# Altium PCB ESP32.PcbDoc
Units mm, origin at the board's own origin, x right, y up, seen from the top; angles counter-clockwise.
Board outline 55.37 x 35.69 mm, 2 copper layers (Top Layer, Bottom Layer); 35 components, 23 nets, 179 pads, 51 vias.
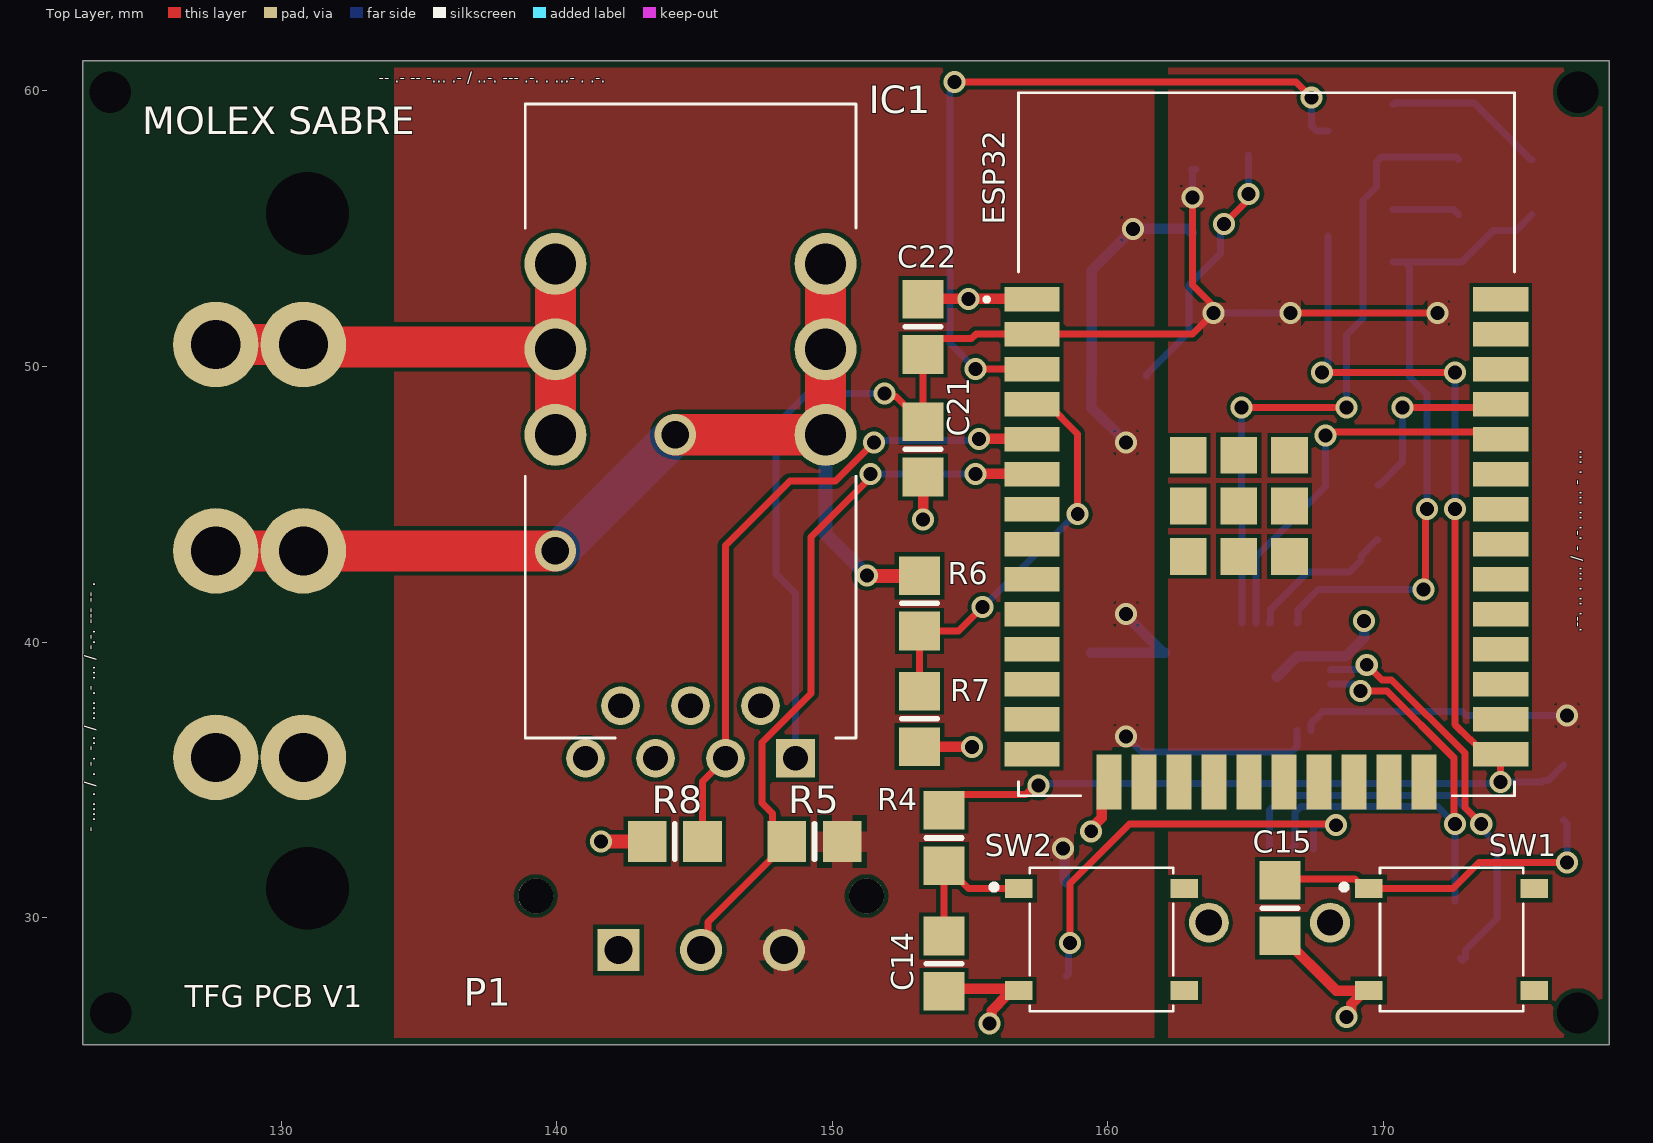
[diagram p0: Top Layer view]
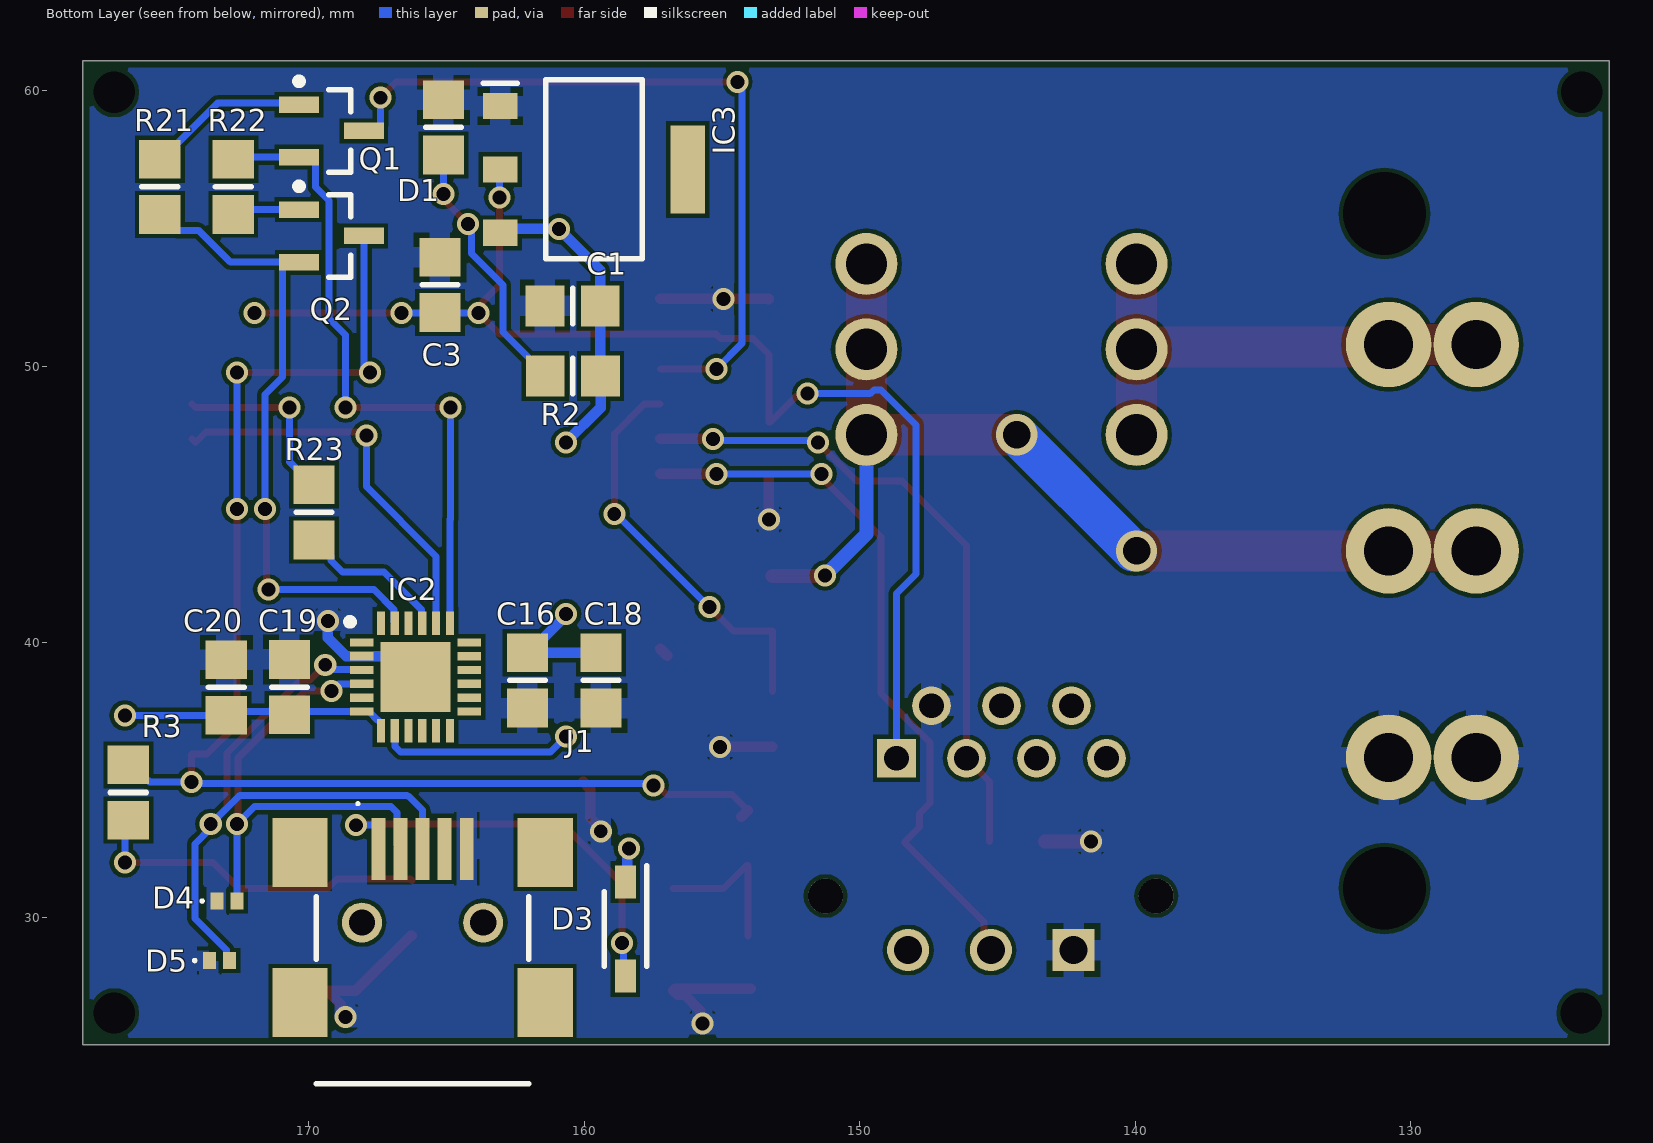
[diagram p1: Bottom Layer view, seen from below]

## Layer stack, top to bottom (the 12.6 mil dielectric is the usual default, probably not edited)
Top Solder: solder mask 0.0102, Solder Resist, Dk 3.5
Top Layer: signal copper 0.0356
Dielectric 1: dielectric 0.32, FR-4, Dk 4.8
Bottom Layer: signal copper 0.0356
Bottom Solder: solder mask 0.0102, Solder Resist, Dk 3.5

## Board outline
122.809,25.4 178.181,25.4 178.181,61.087 122.809,61.087

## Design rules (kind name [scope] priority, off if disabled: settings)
BoardOutlineClearance [All] p1: gap=0.25 ignorepadtopadclearanceinfootprint=FALSE except(0: Arc-SplitContinuation Track-SplitContinuation SMDPad-SplitContinuation THPad-SplitContinuation Via-SplitContinuation Fill-SplitContinuation Poly-SplitContinuation Region-SplitContinuation Text-SplitContinuation)
Clearance Clearance-xPP-xTP-xTT [All] p1: gap=0.15 ignorepadtopadclearanceinfootprint=FALSE except(0: Arc-Hole Track-Hole SMDPad-Hole THPad-Hole Via-Hole Fill-Hole Poly-Hole Region-Hole Text-Hole)
ComponentClearance [All] p1: gap=0.25 collisioncheckmode=3 verticalgap=0.25 showdistances=FALSE
DiffPairsRouting [All] p1: maxlimit=0.25 minlimit=0.25 mostfreqgap=0.25 toplayer_minwidth=0.381 toplayer_maxwidth=0.381 toplayer_prefwidth=0.381 bottomlayer_minwidth=0.381 bottomlayer_maxwidth=0.381 bottomlayer_prefwidth=0.381 maxuncoupledlength=12.5
Height [All] p1: minheight=0 maxheight=100 prefheight=12.5
HoleSize HoleSize-PTH [All] p1: absolutevalues=TRUE maxlimit=4.01 minlimit=0.25 maxpercent=80.000 minpercent=20.000
HoleToHoleClearance [All] p1: gap=0.35 allowstackedmicrovias=TRUE
MinimumAnnularRing "Minimum IAR  >0.45mm" [((ObjectKind = 'Pad') OR (ObjectKind = 'Via')) And (Layer = 'MultiLayer') And (HoleDiameter > AsMM(0.45))] p1: minimumring=0.175 // minimum inner annular ring for pads > 0.45mm finished hole size
MinimumAnnularRing "Minimum IAR <=0.45mm" [((ObjectKind = 'Pad') OR (ObjectKind = 'Via')) And (Layer = 'MultiLayer') And (HoleDiameter <= AsMM(0.45))] p2: minimumring=0.175 // minimum inner annular ring for pads <= 0.45mm finished hole size
MinimumSolderMaskSliver [All] p1: minsoldermaskwidth=0.08
PlaneClearance PlaneClearance-IPI [All] p1: clearance=0.25
PlaneConnect [All] p1: planeconnectstyle=Relief reliefexpansion=0.175 reliefentries=4 reliefconductorwidth=0.2 reliefairgap=0.2
PolygonConnect PolygonConnect-xTW [All] p1: connectstyle=Relief reliefconductorwidth=0.762 reliefentries=4 polygonreliefangle="90 Angle" airgapwidth=0.2
RoutingCorners [All] p1: cornerstyle=45-Degree minsetback=2.5 maxsetback=2.5
RoutingVias "RoutingVias > 0.45mm" [(ObjectKind = 'Via') And (HoleDiameter > AsMM(0.45))] p1: holewidth=0.5 width=0.85 viastyle="Through Hole" minholewidth=0.5 minwidth=0.8 maxholewidth=0.9 maxwidth=1.25 // finishet hole size > 0.45mm
RoutingVias "RoutingVias <= 0.45mm" [(ObjectKind = 'Via') And (HoleDiameter <= AsMM(0.45))] p2: holewidth=0.3 width=0.65 viastyle="Through Hole" minholewidth=0.3 minwidth=0.6 maxholewidth=0.45 maxwidth=0.8 // finishet hole size <= 0.45mm
SilkToSilkClearance [All] p1: silktosilkclearance=0.2
SilkToSolderMaskClearance SilkscreenOverComponentPads [IsPad] p1: minsilkscreentomaskgap=0.2 clearancetoexposedcopper=TRUE
SolderMaskExpansion [All] p1: expansion=0 istentingtop=FALSE
UnRoutedNet [All] p1: checkbadconnections=TRUE
Width Width-xTW [All] p1: maxlimit=3 minlimit=0.15 preferedwidth=0.254
18 further rules are at their usual default settings.

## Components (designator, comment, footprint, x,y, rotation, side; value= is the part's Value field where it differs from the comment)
C1 "Cap" 6-0805_M 160.417,52.197 r180 bottom value=10uF
C3 "Cap" 6-0805_M 165.227,52.959 r270 bottom value=22uF
C14 "Cap" 6-0805_M 154.051,28.337 r90 top value=1nF
C15 "Cap" 6-0805_M 166.243,30.353 r90 top value=1nF
C16 "Cap" 6-0805_M 162.052,38.608 r90 bottom value=0.1uF
C18 "Cap" 6-0805_M 159.385,38.608 r90 bottom value=10uF
C19 "Cap" 6-0805_M 170.688,38.37 r270 bottom value=10uF
C20 "Cap" 6-0805_M 172.974,38.354 r270 bottom value=0.1uF
C21 "Cap" 6-0805_M 153.289,46.99 r90 top value=100uF
C22 "Cap" 6-0805_M 153.289,51.435 r270 top value=1uF
D1 "LED0" 6-0805_M 165.1,58.674 r90 bottom
D3 "1N5819HW-7-F" SOD3716X145N 158.496,29.591 r270 bottom
D4 "ESD5581N2T5G" ESD5581N2T5G 172.958,30.607 r180 bottom
D5 "ESD5581N2T5G" ESD5581N2T5G 173.228,28.448 r180 bottom
ESP32 "ESP32-WROOM-32D__4MB_PS_" ESP32WROOM32D4MBPS 165.75,47.18 r0 top
IC1 "HO_8-NP_SP33_1000" HO8NPSP33-1000 148.664,35.785 r90 top
IC2 "CP2102N-A02-GQFN24R" QFN50P400X400X80-25N-D 166.116,38.735 r180 bottom
IC3 "NCP1117ST33T3G" SOT230P700X180-4N 159.639,57.15 r180 bottom
J1 "10033526-N3212MLF" 10033526N3212MLF 165.857,33.174 r180 bottom
"MOLEX SABRE" "PANEL" 43160-4303 134.985,29.017 r90 top
P1 "DS18B20" 43650-0315 145.24,28.829 r180 top
Q1 "NPN" SOT-23_M 169.164,58.547 r180 bottom
Q2 "NPN" SOT-23_M 169.164,54.737 r180 bottom
R2 "Res1" 6-0805_M 160.401,49.657 r180 bottom value=2K
R3 "Res1" 6-0805_M 176.53,34.544 r90 bottom value=470
R4 "Res1" 6-0805_M 154.051,32.893 r90 top value=470
R5 "Res2" 6-0805_M 149.352,32.766 r180 top value=4.7K
R6 "Res2" 6-0805_M 153.162,41.402 r90 top value=189K
R7 "Res2" 6-0805_M 153.162,37.211 r90 top value=11K
R8 "Res2" 6-0805_M 144.288,32.766 r0 top value=10K
R21 "Res1" 6-0805_M 175.387,56.515 r90 bottom value=12K
R22 "Res1" 6-0805_M 172.72,56.515 r270 bottom value=12K
R23 "Res1" 6-0805_M 169.799,44.704 r90 bottom value=470
SW1 "PTS526_SK15_SMTR2_LFS" PTS526SK15SMTR2LFS 172.466,29.21 r0 top
SW2 "PTS526_SK15_SMTR2_LFS" PTS526SK15SMTR2LFS 159.766,29.21 r0 top

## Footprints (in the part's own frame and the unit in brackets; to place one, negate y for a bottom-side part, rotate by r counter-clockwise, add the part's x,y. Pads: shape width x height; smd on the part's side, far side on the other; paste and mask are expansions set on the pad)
6-0805_M [mm] "Chip Resistor, Body 2.0x1.2mm, IPC Low Density"
  rect 1.4x1.5 smd: 1(-1,0) 2(1,0)
  silkscreen extent 0,-0.65 0,0.65, body extent -1.07,-0.7 1.07,0.7, height 0.7
43160-4303 [mm] "Molex SABRE 3pin VERTICAL"
  round 3.1 hole 1.78: 1(6.8,4.175) 1(6.8,7.355) 2(14.29,4.175) 2(14.29,7.355) 3(21.78,4.175) 3(21.78,7.355)
  round 1.524 hole 3: 14(2.05,4.025) 14(26.53,4.025)
  body extent 0.01,-2.22 28.59,11.17, height 14.88
43650-0315 [mm]
  rect 1.53x1.53 hole 1.02: 1(3,0)
  round 1.53 hole 1.02: 2(0,0) 3(-3,0)
  round 1.27 hole 1.27: 5(-6,-1.96) 5(6,-1.96)
  body extent -6.32,-2.47 6.33,3.14, height 9.95
10033526N3212MLF [mm]
  rect 0.5x2.25 smd: 1(-1.6,-0.675) 2(-0.8,-0.675) 3(0,-0.675) 4(0.8,-0.675) 5(1.6,-0.675)
  rect 2x2.5 smd: 6(4.45,-0.8) 7(4.45,-6.25) 8(-4.45,-6.25) 9(-4.45,-0.8)
  round 1.45 hole 0.95: 10(-2.2,-3.35) 11(2.2,-3.35)
  silkscreen extent -3.85,-9.2 3.85,1.01, body extent -4.95,-9.11 4.95,0.22, height 3.95
ESD5581N2T5G [mm]
  rect 0.47x0.6 smd: 1(-0.365,0) 2(0.365,0)
  silkscreen extent -0.95,-0.05 -0.85,0.05, body extent -0.55,-0.3 0.55,0.3, height 0.5
ESP32WROOM32D4MBPS [mm]
  rect 2x0.9 smd: 1(-8.5,5.26) 2(-8.5,3.99) 3(-8.5,2.72) 4(-8.5,1.45) 5(-8.5,0.18) 6(-8.5,-1.09) 7(-8.5,-2.36) 8(-8.5,-3.63) 9(-8.5,-4.9) 10(-8.5,-6.17) 11(-8.5,-7.44) 12(-8.5,-8.71) 13(-8.5,-9.98) 14(-8.5,-11.25) 25(8.5,-11.25) 26(8.5,-9.98) 27(8.5,-8.71) 28(8.5,-7.44) 29(8.5,-6.17) 30(8.5,-4.9) 31(8.5,-3.63) 32(8.5,-2.36) 33(8.5,-1.09) 34(8.5,0.18) 35(8.5,1.45) 36(8.5,2.72) 37(8.5,3.99) 38(8.5,5.26)
  rect 0.9x2 smd: 15(-5.715,-12.25) 16(-4.445,-12.25) 17(-3.175,-12.25) 18(-1.905,-12.25) 19(-0.635,-12.25) 20(0.635,-12.25) 21(1.905,-12.25) 22(3.175,-12.25) 23(4.445,-12.25) 24(5.715,-12.25)
  rect 1.33x1.33 smd: 39(-2.835,-0.405) 40(-1,-0.405) 41(0.835,-0.405) 42(0.835,-2.24) 43(-1,-2.24) 44(-2.835,-2.24) 45(-2.835,-4.075) 46(-1,-4.075) 47(0.835,-4.075)
  silkscreen extent -10.2,-12.75 9,12.75, body extent -9,-12.75 9,12.75, height 3.3
HO8NPSP33-1000 [mm]
  rect 1.4x1.4 hole 0.9: 1(0,0)
  round 1.4 hole 0.9: 2(1.905,1.27) 3(0,2.54) 4(1.905,3.81) 5(0,5.08) 6(1.905,6.35) 7(0,7.62)
  round 2.25 hole 1.5: 8(11.736,8.71) 9(14.835,8.71) 10(17.936,8.71) 11(17.936,-1.09) 12(14.836,-1.09) 13(11.736,-1.09)
  silkscreen extent 0.74,-2.19 23.74,9.81, body extent -0.16,-2.16 23.78,9.84, height 11.9
PTS526SK15SMTR2LFS [mm]
  rect 1x0.7 smd: 1(-3,1.85) 2(3,1.85) 3(-3,-1.85) 4(3,-1.85)
  silkscreen extent -4,-2.6 2.6,2.6, body extent -3.43,-2.6 3.43,2.6, height 1.75
QFN50P400X400X80-25N-D [mm]
  rect 0.85x0.3 smd: 1(-1.95,1.25) 2(-1.95,0.75) 3(-1.95,0.25) 4(-1.95,-0.25) 5(-1.95,-0.75) 6(-1.95,-1.25) 13(1.95,-1.25) 14(1.95,-0.75) 15(1.95,-0.25) 16(1.95,0.25) 17(1.95,0.75) 18(1.95,1.25)
  rect 0.3x0.85 smd: 7(-1.25,-1.95) 8(-0.75,-1.95) 9(-0.25,-1.95) 10(0.25,-1.95) 11(0.75,-1.95) 12(1.25,-1.95) 19(1.25,1.95) 20(0.75,1.95) 21(0.25,1.95) 22(-0.25,1.95) 23(-0.75,1.95) 24(-1.25,1.95)
  rect 2.55x2.55 smd: 25(0,0)
  silkscreen extent -2.5,1.88 -2.25,2.12, body extent -2.05,-2.05 2.05,2.05, height 0.8
SOD3716X145N [mm]
  rect 1.2x0.75 smd: 1(-1.7,0) 2(1.7,0)
  silkscreen extent -2.3,-0.77 1.35,0.77, body extent -1.85,-0.77 1.85,0.77, height 1.45
SOT230P700X180-4N [mm]
  rect 1.25x0.95 smd: 1(-3.4,2.3) 2(-3.4,0) 3(-3.4,-2.3)
  rect 1.25x3.2 smd: 4(3.4,0)
  silkscreen extent -4.03,-3.25 1.75,3.25, body extent -3.5,-3.25 3.5,3.25, height 1.8
SOT-23_M [mm] "SOT23, 3-Leads, Body 2.9x1.3mm, Pitch 0.95mm, Lead Span 2.5mm, IPC Low Density"
  rect 1.45x0.6 smd: 1(-1.175,0.95) 2(-1.175,-0.95) 3(1.175,0)
  silkscreen extent -1.3,-1.5 0.7,1.92, body extent -0.7,-1.5 0.7,1.5, height 1.1

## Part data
C1 C3 C14 C15 C16 C18 C19 C20 C21 C22: "Capacitor"
D1: "Typical INFRARED GaAs LED"
D3: "Diode", Manufacturer_Name="Diodes Inc.", Mouser2 Part Number=621-1N5819HW-F
D4 D5: "TVS Diode (Bi-directional)", Manufacturer_Name="ON Semiconductor", Mouser2 Part Number=863-ESD5581N2T5G
ESP32: "Integrated Circuit", Manufacturer_Name="Espressif Systems", Manufacturer_Part_Number="ESP32-WROOM-32D (4MB PS)"
IC1: "Integrated Circuit", Manufacturer_Name=LEM, Manufacturer_Part_Number="HO 10-P/SP33"
IC2: "Integrated Circuit", Manufacturer_Name="Silicon Labs", Mouser2 Part Number=634-CP2102NA02QFN24R
IC3: "Integrated Circuit", Manufacturer_Name="ON Semiconductor", Mouser2 Part Number=863-NCP1117ST33T3G
J1: "Connector", Manufacturer_Name=Amphenol, Mouser2 Part Number=649-10033526N3212MLF
"MOLEX SABRE": library part "Molex SABRE 3pin vertical", "Molex SABRE 3pin vertical connector"
P1: library part "Header 3", "Header, 3-Pin"
Q1 Q2: "NPN Bipolar Transistor"
R2 R3 R4 R5 R6 R7 R8 R21 R22 R23: "Resistor"
SW1 SW2: "Switch", Manufacturer_Name="C & K COMPONENTS", Manufacturer_Part_Number="PTS526 SK15 SMTR2 LFS", Mouser2 Part Number=611-PTS526SK15SMR2L

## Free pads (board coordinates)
  round 1 hole 1.5: 8(123.8,59.944) 9(177.038,26.543) 10(177.038,59.944) 11(123.825,26.543)

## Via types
v1: diameter 0.8, hole 0.5, Top Layer to Bottom Layer, 49 vias
v2: diameter 1.5, hole 1, Top Layer to Bottom Layer, 2 vias

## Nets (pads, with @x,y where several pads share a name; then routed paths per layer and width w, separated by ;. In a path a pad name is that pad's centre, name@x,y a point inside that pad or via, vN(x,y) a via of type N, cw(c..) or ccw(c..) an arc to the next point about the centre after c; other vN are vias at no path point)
+3.3: C3.2 C19.2 C20.2 C21.2 C22.2 ESP32.2 IC1.1 IC2.6 IC2.7 IC3.2 | length 56
  Top Layer w0.254: v1(151.892,49.022) 151.996,48.918 152.311,48.918 153.239,47.99 C21.2 C22.2 153.862,51.008 155.046,51.008 155.219,51.181 157.226,51.181 163.068,51.181 v1(163.83,51.943) 163.83,52.197 163.068,52.959 v1(163.068,56.134) ; v1(166.624,51.943) v1(171.958,51.943)
  Bottom Layer w0.254: IC1.1 148.664,41.764 147.955,42.473 147.955,47.879 149.225,49.149 149.479,49.149 149.606,49.022 v1(151.892,49.022) ; v1(163.068,56.134) 163.068,57.121 IC3.2 IC3.2@163.189,57.15 ; v1(163.83,51.943) 165.211,51.943 C3.2 165.243,51.943 v1(166.624,51.943) ; IC2.7 167.366,37.06 167.489,37.183 167.506,37.183 167.768,37.445 167.768,37.462 167.791,37.485 IC2.6 170.303,37.485 170.307,37.481 172.847,37.481 C20.2 172.99,37.338 v1(176.657,37.338)
+5: C1.2 C16.2 C18.2 D3.1 IC2.8 IC3.3 P1.3 R2.2 R5.1 | length 24.1
  Bottom Layer w0.254: v1(160.655,36.576) 161.212,36.019 166.657,36.019 166.856,36.219 166.856,36.775 IC2.8
  Bottom Layer w0.381: v1(158.369,32.512) 158.433,32.448 158.433,31.354 D3.1 ; C18.2 C16.2@162.002,39.608 ; v1(160.655,41.021) 160.655,40.955 C16.2@162.002,39.608 ; v1(160.655,47.244) 159.401,48.498 R2.2 159.417,49.673 C1.2 159.417,53.499 v1(160.909,54.991) 162.898,54.991 IC3.3 ; C16.2 C16.2@162.002,39.608
Current: ESP32.5 IC1.3 R8.2 | length 23.8
  Top Layer w0.254: R8.2 145.288,34.949 IC1.3 146.124,43.508 148.463,45.847 150.114,45.847 v1(151.511,47.244)
  Top Layer w0.381: v1(155.321,47.371) ESP32.5@157.226,47.371
  Bottom Layer w0.254: v1(151.511,47.244) 151.575,47.307 155.257,47.307 v1(155.321,47.371)
D+: D5.2 IC2.3 J1.3 | length 24.7
  Top Layer w0.254: v1(169.388,39.177) 169.4,39.177 169.946,38.631 170.29,38.631 172.949,35.972 172.949,33.995 v1(173.543,33.401)
  Bottom Layer w0.254: J1.3 165.857,33.904 166.347,34.394 166.37,34.394 166.416,34.44 172.504,34.44 v1(173.543,33.401) 173.543,33.253 174.117,32.679 174.117,29.972 172.971,28.826 172.971,28.556 D5.2 D5.2@172.792,28.519 ; IC2.3 168.089,39.008 169.219,39.008 v1(169.388,39.177)
D-: D4.2 IC2.4 J1.2 | length 18.3
  Top Layer w0.254: v1(169.164,38.227) 170.123,38.227 172.545,35.805 172.545,33.442 v1(172.589,33.397)
  Bottom Layer w0.254: J1.2 166.78,32.622 166.78,33.811 167.005,34.036 171.958,34.036 172.589,33.405 v1(172.589,33.397) ; IC2.4 168.068,38.483 168.908,38.483 v1(169.164,38.227) ; D4.2 v1@172.593,33.401
DATA: ESP32.6 P1.2 R5.2 | length 26.4
  Top Layer w0.254: P1.2 145.484,29.073 145.484,29.848 148.352,32.716 R5.2 147.828,33.29 147.828,33.782 147.447,34.163 147.447,36.361 149.225,38.139 149.225,43.815 151.384,45.974 v1(151.384,46.101)
  Top Layer w0.381: v1(155.194,46.101) ESP32.6@157.226,46.101
  Bottom Layer w0.254: v1(151.384,46.101) v1(155.194,46.101)
DTR: IC2.23 Q2.2 R21.1 | length 23.4
  Top Layer w0.254: v1(171.45,41.91) 171.513,41.974 171.513,44.767 v1(171.577,44.831)
  Bottom Layer w0.254: IC2.23 166.889,40.708 166.889,41.175 167.624,41.91 v1(171.45,41.91) ; Q2.2 Q2.2@170.764,53.787 ; v1(171.577,44.831) 171.577,48.976 170.937,49.616 170.937,53.614 Q2.2@170.764,53.787 ; R21.1 174.814,54.942 173.989,54.942 172.834,53.787 Q2.2@170.764,53.787
EN: ESP32.3 Q1.3 | length 27.8
  Top Layer w0.254: v1(154.432,60.325) 166.814,60.325 v1(167.386,59.753) ; v1(155.194,49.911) ESP32.3@157.226,49.911
  Bottom Layer w0.254: v1(154.432,60.325) 154.263,60.156 154.263,50.842 v1(155.194,49.911) ; v1(167.386,59.753) 167.386,59.563 167.391,59.558 167.391,58.72 167.564,58.547 Q1.3
GND: "MOLEX SABRE.1" C1.1 C3.1 C14.1 C15.1 C16.1 C18.1 C19.1 C20.1 C21.1 C22.1 D1.2 D4.1 D5.1 ESP32.1 ESP32.15 IC1.2 IC2.2 IC2.25 IC3.1 J1.5 P1.1 R7.1 R8.1 SW1.3 SW2.3 | length 25.3
  Top Layer w0.381: R7.1 153.178,36.195 v1(155.067,36.195) ; v1(153.289,44.45) C21.1 ; C22.1 153.305,52.451 v1(154.94,52.451) ESP32.1@157.226,52.451 ; C14.1@153.945,27.432 156.694,27.432 SW2.3 156.606,27.2 156.352,27.2 155.782,26.63 155.782,26.242 v1(155.702,26.162) ; v1(159.391,33.136) 159.391,33.249 159.775,33.634 159.775,34.67 ESP32.15 ; C15.1 166.293,29.353 168.286,27.36 169.316,27.36 168.822,26.866 168.822,26.568 v1(168.656,26.402)
  Top Layer w0.5: v1(141.605,32.766) R8.1
  Bottom Layer w0.381: IC2.25 166.866,39.485 IC2.2 168.076,39.495 168.632,39.495 169.291,40.153 v1(169.291,40.767)
IO0: ESP32.25 Q2.3 R3.2 R4.2 | length 49.2
  Top Layer w0.254: R4.2 154.624,34.466 157,34.466 157.332,34.798 v1(157.48,34.798) ; v1(167.767,49.784) v1(172.593,49.784) ; v1(172.593,44.831) 172.593,37.002 173.129,36.467 173.15,36.467 173.676,35.941 174.226,35.941 174.244,35.923 v1(174.244,34.925)
  Top Layer w0.381: R4.2 R4.2@154.289,33.655
  Bottom Layer w0.254: v1(157.48,34.798) 157.543,34.861 174.18,34.861 v1(174.244,34.925) 175.758,34.925 175.804,34.971 175.957,34.971 R3.2 ; v1(167.767,49.784) 167.979,49.996 167.979,52.706 167.989,52.716 Q2.3 ; v1(172.593,44.831) v1(172.593,49.784)
NetC14_2: C14.2 R4.1 SW2.1 | length 5.6
  Top Layer w0.254: C14.2 R4.1 154.101,31.893 154.934,31.06 SW2.1
NetC15_2: C15.2 R3.1 SW1.1 | length 12.6
  Top Layer w0.254: C15.2 166.301,31.411 168.965,31.411 169.316,31.06 SW1.1 172.514,31.06 173.458,32.004 v1(176.657,32.004)
  Bottom Layer w0.254: R3.1 176.657,33.417 v1(176.657,32.004)
NetD1_1: D1.1 R2.1 | length 9.5
  Top Layer w0.254: v1(164.214,55.174) 165.1,56.06 v1(165.1,56.261)
  Bottom Layer w0.254: R2.1 161.401,49.707 162.941,51.247 162.941,52.959 164.084,54.102 164.084,55.044 v1(164.214,55.174) ; v1(165.1,56.261) D1.1
NetIC1_8: "MOLEX SABRE.3" IC1.8 IC1.9 IC1.10 | length 18.6
  Top Layer w1.5: 127.63,50.797 130.81,50.797 130.899,50.708 139.866,50.708 IC1.9 ; IC1.8 IC1.9 ; IC1.10 IC1.9
NetIC2_21: IC2.21 R23.1 | length 5.6
  Bottom Layer w0.254: IC2.21 165.889,40.708 165.889,41.175 167.259,42.545 168.759,42.545 169.176,42.962 169.176,43.131 169.749,43.704 R23.1
NetQ1_1: Q1.1 R21.2 | length 5.9
  Bottom Layer w0.254: Q1.1 170.405,59.563 173.289,59.563 175.337,57.515 R21.2
NetQ2_1: Q2.1 R22.2 | length 2.5
  Bottom Layer w0.254: Q2.1 172.548,55.687 R22.2
RTS: IC2.19 Q1.2 R22.1 | length 24.1
  Top Layer w0.254: v1(164.846,48.514) v1(168.656,48.514)
  Bottom Layer w0.254: v1(164.846,48.514) 164.846,44.45 164.866,44.47 IC2.19 ; v1(168.656,48.514) 168.656,51.139 169.251,51.734 169.251,56.015 169.741,56.506 169.741,57.424 169.914,57.597 Q1.2 172.638,57.597 R22.1
RXD: ESP32.34 IC2.20 | length 14.5
  Top Layer w0.254: v1(167.894,47.498) 168.021,47.625 173.718,47.625 174.099,47.244 ESP32.34@174.226,47.371
  Bottom Layer w0.254: IC2.20 165.366,43.113 167.894,45.641 v1(167.894,47.498)
TXD: ESP32.35 R23.2 | length 6.8
  Top Layer w0.254: v1(170.688,48.514) 174.099,48.514 ESP32.35@174.226,48.641
  Bottom Layer w0.254: R23.2 169.849,45.704 170.688,46.543 v1(170.688,48.514)
USB_PWR: D3.2 J1.1 | length 15.6
  Top Layer w0.254: v1(158.623,29.083) 158.623,31.242 160.782,33.401 168.233,33.401 v1(168.275,33.359)
  Bottom Layer w0.254: D3.2 158.559,27.955 158.559,29.019 v1(158.623,29.083) ; J1.1 167.457,33.236 167.58,33.359 v1(168.275,33.359)
V+: "MOLEX SABRE.2" IC1.11 IC1.12 IC1.13 R6.2 | length 37.7
  Top Layer w0.5: v1(151.257,42.418) 151.273,42.402 R6.2
  Top Layer w1.5: 127.63,43.307 130.81,43.307 v2(139.954,43.307) ; v2(144.295,47.521) IC1.13 IC1.12 IC1.11
  Bottom Layer w0.5: IC1.13 149.754,43.921 v1(151.257,42.418)
  Bottom Layer w1.5: v2(139.954,43.307) 140.081,43.307 v2(144.295,47.521)
Voltage: ESP32.4 R6.1 R7.2 | length 14.5
  Top Layer w0.254: R7.2 R6.1 154.575,40.402 v1(155.448,41.275) ; ESP32.4 157.822,48.63 158.9,47.552 v1(158.9,44.65)
  Bottom Layer w0.254: v1(155.448,41.275) 155.461,41.275 158.763,44.577 v1@158.776,44.577
pads on no net: "MOLEX SABRE.14" ESP32.7 ESP32.8 ESP32.9 ESP32.10 ESP32.11 ESP32.12 ESP32.13 ESP32.14 ESP32.16 ESP32.17 ESP32.18 ESP32.19 ESP32.20 ESP32.21 ESP32.22 ESP32.23 ESP32.24 ESP32.26 ESP32.27 ESP32.28 ESP32.29 ESP32.30 ESP32.31 ESP32.32 ESP32.33 ESP32.36 ESP32.37 ESP32.38 ESP32.39 ESP32.40 ESP32.41 ESP32.42 ESP32.43 ESP32.44 ESP32.45 ESP32.46 ESP32.47 IC1.4 IC1.5 IC1.6 IC1.7 IC2.1 IC2.5 IC2.9 IC2.10 IC2.11 IC2.12 IC2.13 IC2.14 IC2.15 IC2.16 IC2.17 IC2.18 IC2.22 IC2.24 IC3.4 J1.4 J1.6 J1.7 J1.8 J1.9 J1.10 J1.11 P1.5 SW1.2 SW1.4 SW2.2 SW2.4
copper on no net: | length 0.4
  Top Layer w0.381: 156.972,39.497 157.226,39.751

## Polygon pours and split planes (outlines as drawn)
GND on Bottom Layer "GND" (solid, pour order 0): 121.158,69.676 121.158,22.86 180.594,22.86 180.721,22.733 180.721,69.088
+5 on Top Layer "+5" (solid, pour order 3): 161.671,62.881 161.671,24.003 159.639,21.971 134.112,21.971 134.112,63.881 145.542,64.77
+3.3 on Top Layer "+3.3" (solid, pour order 2): 162.179,62.232 162.179,23.749 181.864,23.749 181.864,65.532

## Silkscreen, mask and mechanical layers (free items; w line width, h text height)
Top Overlay:
  text "-- .- -- -... .- / ..-. --- .-. . ...- . .-." at 133.55,60.3 h0.4
  text ".--. .. . ... / - .-. .. ... - . ..." at 177.192,40.359 h0.4 r90
  text "- .... . / . -. -.. / .... .- ... / -.-. --- -- ." at 123.25,33.1 h0.4 r90
  text "TFG PCB V1" at 126.504,26.754 h0.8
